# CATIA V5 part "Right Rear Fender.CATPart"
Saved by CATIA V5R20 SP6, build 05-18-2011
Part number: Right Rear Fender
Bounding box of the stored display mesh (mm): x -496.521 to 425.059, y -80 to 100, z -6.699 to 429.99
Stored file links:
  E:\#03 University\#02 영남 이공대\#01 2021\#02 여름 방학\#01 Documents\K-Move Page02 ASD01\Right Rear Fender.CATPart

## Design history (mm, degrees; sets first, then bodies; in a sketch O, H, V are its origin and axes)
Set1 "Reference Data"
  Point1 "Center Point": (0, 0, 0)
  Plane1 "Plane.1(Y Dir=-80mm)": type Offset, RefPlane zx-plane, Offset 80, reversed
  Plane2 "Plane.2(Y Dir Plane.1=180mm)": type Offset, RefPlane Plane1, Offset 180
  Plane3 "Plane.3(Z Dir=65mm)": type Offset, RefPlane xy-plane, Offset 65
  Line1: type PtDir, LineFirstUpto Plane1, LineSecondUpto Plane2, RefPoint Point1, Direction zx-plane, Start 0, End 20
  Project1: ToProject Line1, Support Plane3
  Extrude1: Element1 Project1, Lim1 600, Lim2 0, Direction yz-plane
Body1 (main body)
  Body2
    Sketch1 on zx-plane, origin (0, 0, 0), H (-1, 0, 0), V (0, 0, 1)
      arc A1 centre (0, 0) radius 430 from (372.3909, 215) to (-425.0588, 65) ccw
      construction line L1 (0, 0) -> (372.3909, 215)
      point P1 (372.3909, 215)
      line L2 (372.3909, 215) -> (496.5212, 0)
      point P2 (496.5212, 0)
      point P4 (-425.0588, 65)
      reference intersected line E1 through (0, 65) direction (-1, 0) from Plane3
      radius A1 = 430
      angle L1 H = 30
      coincidence: P1 A1, P2 H, P1 L2, P4 E1
      tangency: L2 A1
    Pad1: profile Sketch1, direction (0, 1, 0), up to Plane2, opposite side up to Plane1, thin wall 50
    Fillet1: radius 50, on edge [face of Pad1 | face of Pad1]
    Fillet2: radius 30, on edge [start face of Pad1 | face of Pad1]
    Split1: SplitPlane Extrude1
    Shell1: ExtOffset 0, Face (face of Pad1; face of Split1; end face of Pad1), IntOffset 5
  Assemble1: tool Body2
